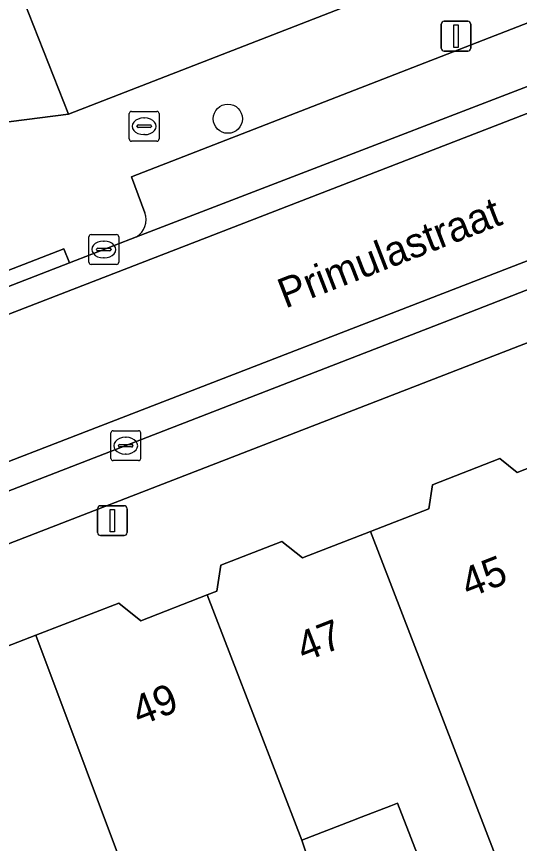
# Model space of a CAD drawing. Extents: x 161692 to 162379, y 380760 to 381678.
# Drawn here: x 161866.11 to 161882.98, y 381183.08 to 381210.82 of the extents above; entities that cross this region are included whole.
import ezdxf

# ---------------------------------------------------------------- set-up
doc = ezdxf.new("R2010")
doc.units = 0
for name, color, linetype in [('IMGEO_Boom', 7, 'Continuous'), ('IMGEO_Brandkraan', 7, 'Continuous'), ('IMGEO_Erf', 7, 'Continuous'), ('IMGEO_Kolk', 7, 'Continuous'), ('IMGEO_Lichtmast', 7, 'Continuous'), ('IMGEO_Openbare_ruimte_label', 7, 'Continuous'), ('IMGEO_Pand', 7, 'Continuous'), ('IMGEO_Pand_nummerreeks', 7, 'Continuous'), ('IMGEO_Parkeervlak_open', 7, 'Continuous'), ('IMGEO_Rijbaan_lokaal_open', 7, 'Continuous'), ('IMGEO_Voetpad_open', 7, 'Continuous')]:
    doc.layers.add(name, color=color, linetype=linetype)

msp = doc.modelspace()

# ---------------------------------------------------------------- linework, layer by layer
at = {"layer": 'IMGEO_Boom'}
msp.add_circle((161873.199, 381207.389), 0.489, dxfattribs=at)
at = {"layer": 'IMGEO_Brandkraan'}
for p, q in [((161869.965, 381207.636), (161870.817, 381207.636)), ((161869.89, 381206.71), (161869.89, 381207.562)), ((161870.378, 381207.416), (161870.403, 381207.416)), ((161870.891, 381207.562), (161870.891, 381206.71)), ((161870.149, 381207.13), (161870.149, 381207.142)), ((161870.587, 381207.093), (161870.189, 381207.093)), ((161870.192, 381207.179), (161870.59, 381207.179)), ((161870.633, 381207.142), (161870.633, 381207.13)), ((161870.401, 381206.856), (161870.376, 381206.856)), ((161870.817, 381206.636), (161869.965, 381206.636))]:
    msp.add_line(p, q, dxfattribs=at)
for points in [[(161869.965, 381207.636), (161870.817, 381207.636)], [(161869.89, 381206.71), (161869.89, 381207.562)], [(161870.891, 381207.562), (161870.891, 381206.71)], [(161870.817, 381206.636), (161869.965, 381206.636)]]:
    msp.add_lwpolyline(points, dxfattribs=at)
for centre, radius, start, end in [((161869.967, 381207.56), 0.0765, 91.552, 178.448), ((161869.967, 381207.56), 0.0765, 91.552, 178.448), ((161870.815, 381207.56), 0.0765, 1.552, 88.448), ((161870.815, 381207.56), 0.0765, 1.552, 88.448), ((161870.189, 381207.139), 0.0403, 85.8775, 175.7526), ((161870.186, 381207.129), 0.0366, 178.938, 274.7102), ((161870.59, 381207.136), 0.043, 264.8664, 352.4533), ((161870.594, 381207.141), 0.0386, 1.7309, 96.639), ((161869.967, 381206.712), 0.0765, 181.552, 268.448), ((161869.967, 381206.712), 0.0765, 181.552, 268.448), ((161870.815, 381206.712), 0.0765, 271.552, 358.448), ((161870.815, 381206.712), 0.0765, 271.552, 358.448)]:
    msp.add_arc(centre, radius, start, end, dxfattribs=at)
for centre, major_axis, ratio, start_param, end_param in [((161870.377, 381207.136), (-0.387, 0.002), 0.722429, 4.712389, 7.853982), ((161870.402, 381207.136), (-0.39, 0.002), 0.717154, 1.570796, 4.712389)]:
    msp.add_ellipse(centre, major_axis=major_axis, ratio=ratio, start_param=start_param, end_param=end_param, dxfattribs=at)
at = {"layer": 'IMGEO_Erf'}
for points in [[(161866.342, 381211.369), (161867.852, 381207.538), (161977.201, 381250)], [(161880.149, 381181.173), (161878.886, 381184.426), (161878.662, 381184.339), (161877.67, 381183.955), (161877.356, 381183.833), (161875.683, 381183.185), (161876.021, 381182.188)]]:
    msp.add_lwpolyline(points, dxfattribs=at)
at = {"layer": 'IMGEO_Kolk'}
for p, q in [((161868.61, 381203.503), (161869.462, 381203.503)), ((161868.535, 381202.577), (161868.535, 381203.429)), ((161869.023, 381203.283), (161869.048, 381203.283)), ((161869.536, 381203.429), (161869.536, 381202.577)), ((161868.794, 381202.997), (161868.794, 381203.009)), ((161869.232, 381202.96), (161868.834, 381202.96)), ((161868.837, 381203.046), (161869.235, 381203.046)), ((161869.278, 381203.009), (161869.278, 381202.997)), ((161869.046, 381202.723), (161869.021, 381202.723)), ((161869.462, 381202.503), (161868.61, 381202.503)), ((161869.271, 381195.996), (161869.271, 381196.848)), ((161869.346, 381196.922), (161870.198, 381196.922)), ((161870.272, 381196.848), (161870.272, 381195.996)), ((161869.759, 381196.702), (161869.784, 381196.702)), ((161869.53, 381196.416), (161869.53, 381196.428)), ((161869.968, 381196.379), (161869.57, 381196.379)), ((161869.573, 381196.465), (161869.971, 381196.465)), ((161870.014, 381196.428), (161870.014, 381196.416)), ((161869.782, 381196.142), (161869.757, 381196.142)), ((161870.198, 381195.922), (161869.346, 381195.922))]:
    msp.add_line(p, q, dxfattribs=at)
for points in [[(161868.61, 381203.503), (161869.462, 381203.503)], [(161868.535, 381202.577), (161868.535, 381203.429)], [(161869.536, 381203.429), (161869.536, 381202.577)], [(161869.462, 381202.503), (161868.61, 381202.503)], [(161869.271, 381195.996), (161869.271, 381196.848)], [(161869.346, 381196.922), (161870.198, 381196.922)], [(161870.272, 381196.848), (161870.272, 381195.996)], [(161870.198, 381195.922), (161869.346, 381195.922)]]:
    msp.add_lwpolyline(points, dxfattribs=at)
for centre, radius, start, end in [((161868.612, 381203.427), 0.0765, 91.552, 178.448), ((161868.612, 381203.427), 0.0765, 91.552, 178.448), ((161869.46, 381203.427), 0.0765, 1.552, 88.448), ((161869.46, 381203.427), 0.0765, 1.552, 88.448), ((161868.834, 381203.006), 0.0403, 85.8775, 175.7526), ((161868.831, 381202.996), 0.0366, 178.938, 274.7102), ((161869.235, 381203.003), 0.043, 264.8664, 352.4533), ((161869.239, 381203.008), 0.0386, 1.7309, 96.639), ((161868.612, 381202.579), 0.0765, 181.552, 268.448), ((161868.612, 381202.579), 0.0765, 181.552, 268.448), ((161869.46, 381202.579), 0.0765, 271.552, 358.448), ((161869.46, 381202.579), 0.0765, 271.552, 358.448), ((161869.348, 381196.846), 0.0765, 91.552, 178.448), ((161869.348, 381196.846), 0.0765, 91.552, 178.448), ((161870.196, 381196.846), 0.0765, 1.552, 88.448), ((161870.196, 381196.846), 0.0765, 1.552, 88.448), ((161869.57, 381196.425), 0.0403, 85.8775, 175.7526), ((161869.567, 381196.415), 0.0366, 178.938, 274.7102), ((161869.971, 381196.422), 0.043, 264.8664, 352.4533), ((161869.975, 381196.427), 0.0386, 1.7309, 96.639), ((161869.348, 381195.998), 0.0765, 181.552, 268.448), ((161869.348, 381195.998), 0.0765, 181.552, 268.448), ((161870.196, 381195.998), 0.0765, 271.552, 358.448), ((161870.196, 381195.998), 0.0765, 271.552, 358.448)]:
    msp.add_arc(centre, radius, start, end, dxfattribs=at)
for centre, major_axis, ratio, start_param, end_param in [((161869.022, 381203.003), (-0.387, 0.002), 0.722429, 4.712389, 7.853982), ((161869.047, 381203.003), (-0.39, 0.002), 0.717154, 1.570796, 4.712389), ((161869.758, 381196.422), (-0.387, 0.002), 0.722429, 4.712389, 7.853982), ((161869.783, 381196.422), (-0.39, 0.002), 0.717154, 1.570796, 4.712389)]:
    msp.add_ellipse(centre, major_axis=major_axis, ratio=ratio, start_param=start_param, end_param=end_param, dxfattribs=at)
at = {"layer": 'IMGEO_Lichtmast'}
for p, q in [((161880.357, 381209.759), (161880.357, 381210.559)), ((161880.357, 381210.559), (161880.357, 381209.759)), ((161880.457, 381210.659), (161881.247, 381210.659)), ((161881.247, 381210.659), (161880.457, 381210.659)), ((161881.347, 381210.559), (161881.347, 381209.759)), ((161881.347, 381209.759), (161881.347, 381210.559)), ((161881.247, 381209.659), (161880.457, 381209.659)), ((161880.457, 381209.659), (161881.247, 381209.659)), ((161868.828, 381193.507), (161868.828, 381194.307)), ((161868.828, 381194.307), (161868.828, 381193.507)), ((161868.928, 381194.407), (161869.718, 381194.407)), ((161869.718, 381194.407), (161868.928, 381194.407)), ((161869.818, 381194.307), (161869.818, 381193.507)), ((161869.818, 381193.507), (161869.818, 381194.307)), ((161869.718, 381193.407), (161868.928, 381193.407)), ((161868.928, 381193.407), (161869.718, 381193.407))]:
    msp.add_line(p, q, dxfattribs=at)
for points in [[(161880.777, 381210.534), (161880.927, 381210.534), (161880.927, 381209.784), (161880.777, 381209.784), (161880.777, 381210.534)], [(161869.248, 381194.282), (161869.398, 381194.282), (161869.398, 381193.532), (161869.248, 381193.532), (161869.248, 381194.282)]]:
    msp.add_lwpolyline(points, dxfattribs=at)
for centre, start, end in [((161880.457, 381210.559), 90, 180), ((161880.457, 381210.559), 90, 180), ((161881.247, 381210.559), 0, 90), ((161881.247, 381210.559), 360, 90), ((161880.457, 381209.759), 180, 270), ((161880.457, 381209.759), 180, 270), ((161881.247, 381209.759), 270, 0), ((161881.247, 381209.759), 270, 0), ((161868.928, 381194.307), 90, 180), ((161868.928, 381194.307), 90, 180), ((161869.718, 381194.307), 0, 90), ((161869.718, 381194.307), 360, 90), ((161868.928, 381193.507), 180, 270), ((161868.928, 381193.507), 180, 270), ((161869.718, 381193.507), 270, 0), ((161869.718, 381193.507), 270, 0)]:
    msp.add_arc(centre, 0.1, start, end, dxfattribs=at)
at = {"layer": 'IMGEO_Pand'}
for points in [[(161883.425, 381195.727), (161882.9, 381195.524), (161882.325, 381195.986), (161880.061, 381195.107), (161879.937, 381194.305), (161877.981, 381193.546), (161882.172, 381182.693), (161882.419, 381182.054), (161883.498, 381179.26), (161885.163, 381179.907), (161884.084, 381182.701), (161887.347, 381183.967), (161886.094, 381187.199), (161886.637, 381187.41)], [(161877.981, 381193.546), (161875.697, 381192.659), (161875.012, 381193.209), (161872.965, 381192.415), (161872.83, 381191.539), (161872.505, 381191.413), (161875.683, 381183.185), (161877.356, 381183.833), (161877.67, 381183.955), (161878.662, 381184.339), (161878.886, 381184.426), (161880.149, 381181.173), (161880.481, 381181.302), (161882.419, 381182.054), (161882.172, 381182.693)], [(161872.505, 381191.413), (161870.281, 381190.549), (161869.541, 381191.144), (161866.752, 381190.062), (161870.13, 381181.053), (161871.822, 381181.71), (161872.232, 381181.869), (161873.282, 381182.277), (161873.851, 381180.812), (161874.372, 381179.47), (161874.895, 381179.673), (161876.108, 381176.549), (161877.72, 381177.175), (161876.644, 381180.352), (161876.457, 381180.901), (161876.181, 381181.716), (161876.021, 381182.188), (161875.683, 381183.185)], [(161866.752, 381190.062), (161860.818, 381187.759), (161863.904, 381179.738), (161864.044, 381179.374), (161865.604, 381175.321), (161868.413, 381176.374), (161867.441, 381178.968), (161870.484, 381180.109), (161870.13, 381181.053)]]:
    msp.add_lwpolyline(points, close=True, dxfattribs=at)
at = {"layer": 'IMGEO_Parkeervlak_open'}
for points in [[(161961.722, 381232.1), (161956.348, 381230.042), (161938.085, 381222.934), (161918.222, 381215.27), (161899.284, 381207.916), (161881.555, 381200.986), (161865.97, 381194.951), (161863.559, 381194.025)], [(161864.233, 381193.647), (161864.586, 381192.643), (161961.787, 381230.31), (161961.409, 381231.377)], [(161897.259, 381214.89), (161896.88, 381215.906), (161869.962, 381205.442), (161870.416, 381204.234)], [(161870.131, 381203.423), (161888.794, 381210.602), (161898.093, 381214.23)]]:
    msp.add_lwpolyline(points, dxfattribs=at)
msp.add_arc((161869.772, 381204.005), 0.683, 301.6559, 19.6193, dxfattribs=at)
at = {"layer": 'IMGEO_Rijbaan_lokaal_open'}
msp.add_lwpolyline([(161935.912, 381223.005), (161936.957, 381223.409), (161935.244, 381227.71), (161934.242, 381227.322), (161860.229, 381198.667), (161861.902, 381194.373)], close=True, dxfattribs=at)
for points in [[(161845.208, 381192.852), (161857.487, 381197.606), (161860.229, 381198.667), (161934.242, 381227.322)], [(161930.566, 381226.829), (161915.285, 381220.839), (161904.026, 381216.527), (161903.292, 381216.246), (161901.517, 381215.566), (161898.974, 381214.574), (161898.093, 381214.23), (161888.794, 381210.602), (161870.131, 381203.423), (161867.88, 381202.555), (161860.061, 381199.525), (161857.385, 381198.488), (161857.163, 381198.402), (161845.391, 381193.932)], [(161935.912, 381223.005), (161861.902, 381194.373), (161859.16, 381193.312), (161846.822, 381188.539)], [(161847.135, 381187.702), (161855.676, 381190.996), (161859.714, 381192.548), (161863.559, 381194.025), (161865.97, 381194.951), (161881.555, 381200.986), (161899.284, 381207.916), (161918.222, 381215.27), (161938.085, 381222.934)]]:
    msp.add_lwpolyline(points, dxfattribs=at)
at = {"layer": 'IMGEO_Voetpad_open'}
for points in [[(161989.239, 381251.642), (161996.14, 381254.262), (162000.537, 381255.938), (162011.205, 381260.006), (162011.546, 381263.36), (162000, 381258.853), (161995.053, 381256.932), (161977.201, 381250), (161867.852, 381207.538), (161863.463, 381206.988), (161860.289, 381205.724), (161856.733, 381203.329), (161790.007, 381177.307), (161770.674, 381180.834), (161767.92, 381176.679), (161769.705, 381176.201), (161769.85, 381176.162)], [(161961.409, 381231.377), (161961.787, 381230.31), (161864.586, 381192.643), (161864.233, 381193.647)], [(161863.218, 381207.613), (161863.463, 381206.988), (161867.852, 381207.538), (161866.342, 381211.369), (161861.388, 381224.149), (161860.324, 381226.916)], [(161870.416, 381204.234), (161869.962, 381205.442), (161896.88, 381215.906), (161897.259, 381214.89)], [(161857.385, 381198.488), (161860.061, 381199.525), (161859.88, 381199.99), (161867.699, 381203.02), (161867.88, 381202.555), (161870.131, 381203.423)], [(161860.818, 381187.759), (161866.752, 381190.062), (161869.541, 381191.144), (161870.281, 381190.549), (161872.505, 381191.413), (161872.83, 381191.539), (161872.965, 381192.415), (161875.012, 381193.209), (161875.697, 381192.659), (161877.981, 381193.546), (161879.937, 381194.305), (161880.061, 381195.107), (161882.325, 381195.986), (161882.9, 381195.524), (161883.425, 381195.727)]]:
    msp.add_lwpolyline(points, dxfattribs=at)
msp.add_lwpolyline([(161867.88, 381202.555), (161867.699, 381203.02), (161859.88, 381199.99), (161860.061, 381199.525)], close=True, dxfattribs=at)
msp.add_arc((161869.772, 381204.005), 0.683, 301.6559, 19.6193, dxfattribs=at)

# ---------------------------------------------------------------- texts
at = {"layer": 'IMGEO_Openbare_ruimte_label'}
msp.add_text('Primulastraat', height=1, rotation=21.1733, dxfattribs=at).set_placement((161875.123, 381201.016))
at = {"layer": 'IMGEO_Pand_nummerreeks'}
for s, p in [('45', (161881.266, 381191.302)), ('47', (161875.746, 381189.156)), ('49', (161870.226, 381187.009))]:
    msp.add_text(s, height=1, rotation=21.2453, dxfattribs=at).set_placement(p)

doc.saveas('drawing.dxf')
